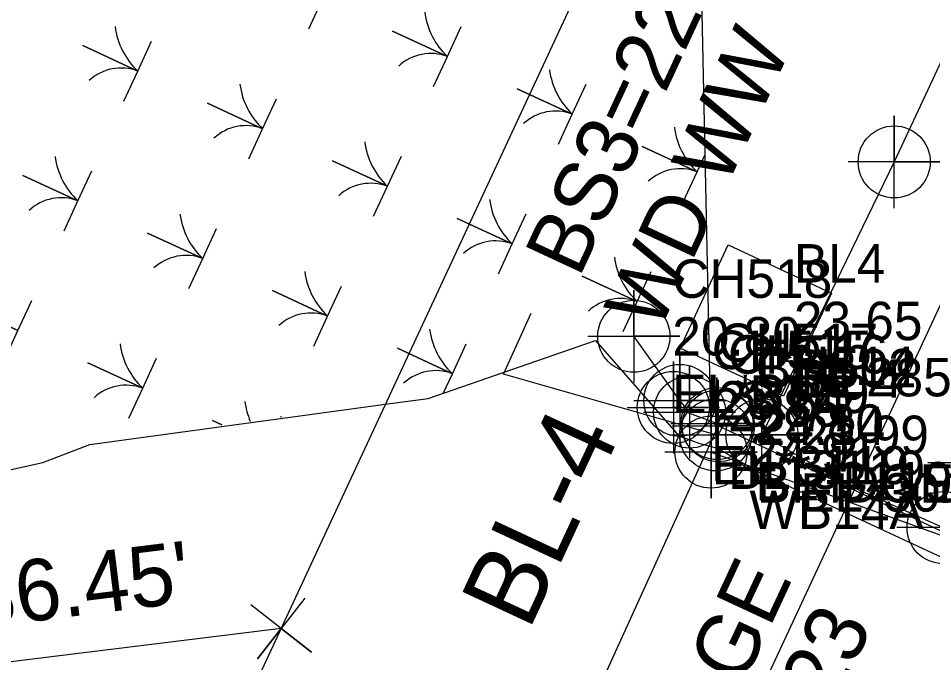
# Model space of a CAD drawing. Extents: x 2532037 to 2533565, y 713396 to 716867.
# Drawn here: x 2532822.3 to 2532881.8, y 715640.6 to 715682.5 of the extents above; entities that cross this region are included whole.
import ezdxf

# ---------------------------------------------------------------- set-up
doc = ezdxf.new("R2010")
doc.units = 0
for name, color, linetype in [('CTL Secondary Horizontal and Vertical CELL', 7, 'Continuous'), ('CTL Secondary Horizontal and Vertical Cogo Comment', 7, 'Continuous'), ('CTL Secondary Horizontal and Vertical Cogo Elevation', 7, 'Continuous'), ('CTL Secondary Horizontal and Vertical Cogo Number', 7, 'Continuous'), ('CTL Secondary Horizontal and Vertical Text', 7, 'Continuous'), ('Exist Environmental Wetland Boundary', 7, 'Continuous'), ('Exist Environmental Wetland Boundary Cogo Comment', 7, 'Continuous'), ('Exist Environmental Wetland Boundary Cogo Elevation', 7, 'Continuous'), ('Exist Environmental Wetland Boundary Cogo Number', 7, 'Continuous'), ('Exist Environmental Wetland Boundary Cogo Point CELL', 7, 'Continuous'), ('Exist Horizontal Alignment', 7, 'Continuous'), ('Exist Hydro Jurisdictional Stream or Body of Water', 7, 'Continuous'), ('Exist Property Corner CELL', 7, 'Continuous'), ('Exist Property Line', 7, 'Continuous'), ('Exist Property Line Text', 7, 'Continuous'), ('Exist Right of Way Line', 7, 'Continuous'), ('Exist Roads Soil', 7, 'Continuous'), ('Exist Roads Soil Cogo Comment', 7, 'Continuous'), ('Exist Roads Soil Cogo Elevation', 7, 'Continuous'), ('Exist Roads Soil Cogo Number', 7, 'Continuous'), ('Exist Roads Soil Cogo Point CELL', 7, 'Continuous'), ('Exist Structure Major Bridge Seat Cogo Point CELL', 7, 'Continuous'), ('Exist Structure Major Bridge Seat Leader', 7, 'Continuous'), ('Exist Structure Major Bridge Seat Top Elevation', 7, 'Continuous'), ('Exist Structure Major Bridge WW', 7, 'Continuous'), ('Exist Structure Major Bridge WW Cogo Comment', 7, 'Continuous'), ('Exist Structure Major Bridge WW Cogo Elevation', 7, 'Continuous'), ('Exist Structure Major Bridge WW Cogo Number', 7, 'Continuous'), ('Exist Structure Major Bridge WW Cogo Point CELL', 7, 'Continuous'), ('Exist Structure Major Bridge WW Text', 7, 'Continuous'), ('Exist Structure Major Deck Tunnel Box Culvert', 7, 'Continuous'), ('Exist Structure Major Deck Tunnel Box Culvert Cogo Comment', 7, 'Continuous'), ('Exist Structure Major Deck Tunnel Box Culvert Cogo Elevation', 7, 'Continuous'), ('Exist Structure Major Deck Tunnel Box Culvert Cogo Number', 7, 'Continuous'), ('Exist Structure Major Deck Tunnel Box Culvert Cogo Point CELL', 7, 'Continuous'), ('Exist Structure Major Deck Tunnel Box Culvert Text', 7, 'Continuous'), ('Scratch_Level_1', 7, 'Continuous')]:
    doc.layers.add(name, color=color, linetype=linetype)

msp = doc.modelspace()

# ---------------------------------------------------------------- linework, layer by layer
at = {"layer": 'CTL Secondary Horizontal and Vertical CELL'}
msp.add_line((2532870.227, 715662.819), (2532870.227, 715662.819), dxfattribs=at)
msp.add_lwpolyline([(2532865.322, 715661.047), (2532868.449, 715667.768), (2532875.181, 715664.636), (2532872.054, 715657.915)], close=True, dxfattribs=at)
at = {"layer": 'Exist Environmental Wetland Boundary'}
for p, q in [((2532866.358, 715700.97), (2532867.338, 715654.282)), ((2532839.356, 715656.559), (2532839.395, 715656.645)), ((2532867.338, 715654.282), (2532887.83, 715646.863))]:
    msp.add_line(p, q, dxfattribs=at)
for points in [[(2532867.177, 715661.939), (2532867.073, 715661.987), (2532867.177, 715661.939)], [(2532835.514, 715656.069), (2532834.912, 715656.346), (2532835.514, 715656.069)]]:
    msp.add_lwpolyline(points, dxfattribs=at)
msp.add_arc((2532841.781, 715658.198), 4.806, 187.34643, 203.20162, dxfattribs=at)
at = {"layer": 'Exist Environmental Wetland Boundary Cogo Point CELL'}
msp.add_lwpolyline([(2532867.338, 715657.282), (2532867.338, 715651.282), (2532867.338, 715654.282), (2532870.338, 715654.282), (2532864.338, 715654.282)], dxfattribs=at)
msp.add_circle((2532867.338, 715654.282), 2.344, dxfattribs=at)
at = {"layer": 'Exist Horizontal Alignment'}
msp.add_line((2532720.816, 715316.862), (2532922.836, 715751.084), dxfattribs=at)
at = {"layer": 'Exist Hydro Jurisdictional Stream or Body of Water'}
msp.add_lwpolyline([(2532806.944, 715649.86), (2532823.862, 715653.608), (2532826.936, 715654.78), (2532846.795, 715657.486), (2532848.935, 715657.763), (2532859.818, 715661.557), (2532865.255, 715655.34), (2532866.545, 715654.873), (2532867.828, 715654.527), (2532870.349, 715653.031), (2532883.272, 715647.025), (2532884.83, 715646.372), (2532885.882, 715645.762), (2532886.539, 715645.426), (2532889.693, 715644.068), (2532889.952, 715644.137), (2532891.522, 715643.982), (2532891.782, 715643.826), (2532896.496, 715640.921), (2532907.078, 715634.646), (2532915.587, 715630.595), (2532919.574, 715628.211), (2532929.47, 715622.835), (2532946.956, 715616.792)], dxfattribs=at)
at = {"layer": 'Exist Property Corner CELL'}
msp.add_line((2532839.376, 715642.813), (2532839.376, 715642.813), dxfattribs=at)
msp.add_lwpolyline([(2532840.913, 715644.784), (2532837.838, 715640.842), (2532839.376, 715642.813), (2532841.347, 715641.275), (2532837.405, 715644.351)], dxfattribs=at)
at = {"layer": 'Exist Property Line'}
msp.add_line((2532839.376, 715642.813), (2532753.576, 715632.211), dxfattribs=at)
at = {"layer": 'Exist Right of Way Line'}
msp.add_line((2532693.616, 715329.517), (2532895.636, 715763.738), dxfattribs=at)
at = {"layer": 'Exist Roads Soil'}
msp.add_lwpolyline([(2533033.002, 715963.552), (2533014.441, 715935.484), (2532992.666, 715901.095), (2532976.471, 715871.314), (2532962.05, 715845.129), (2532943.271, 715807.995), (2532921.982, 715764.363), (2532902.685, 715724.284), (2532889.068, 715694.204), (2532879.255, 715673.169), (2532870.648, 715655.411), (2532876.571, 715652.013), (2532882.435, 715649.375)], dxfattribs=at)
at = {"layer": 'Exist Roads Soil Cogo Point CELL'}
for points in [[(2532879.255, 715670.169), (2532879.255, 715676.169), (2532879.255, 715673.169), (2532882.255, 715673.169), (2532876.255, 715673.169)], [(2532870.648, 715652.411), (2532870.648, 715658.411), (2532870.648, 715655.411), (2532873.648, 715655.411), (2532867.648, 715655.411)], [(2532884.446, 715650.582), (2532884.446, 715656.582), (2532884.446, 715653.582), (2532887.446, 715653.582), (2532881.446, 715653.582)], [(2532882.435, 715646.375), (2532882.435, 715652.375), (2532882.435, 715649.375), (2532885.435, 715649.375), (2532879.435, 715649.375)]]:
    msp.add_lwpolyline(points, dxfattribs=at)
for centre in [(2532879.255, 715673.169), (2532870.648, 715655.411), (2532882.435, 715649.375)]:
    msp.add_circle(centre, 2.344, dxfattribs=at)
at = {"layer": 'Exist Structure Major Bridge Seat Cogo Point CELL'}
msp.add_lwpolyline([(2532864.642, 715655.407), (2532870.642, 715655.407), (2532867.642, 715655.407), (2532867.642, 715658.407), (2532867.642, 715652.407)], dxfattribs=at)
msp.add_lwpolyline([(2532864.642, 715655.407), (2532870.642, 715655.407), (2532867.642, 715655.407), (2532867.642, 715658.407), (2532867.642, 715652.407)], dxfattribs=at)
msp.add_circle((2532867.642, 715655.407), 2.344, dxfattribs=at)
msp.add_circle((2532867.642, 715655.407), 2.344, dxfattribs=at)
at = {"layer": 'Exist Structure Major Bridge Seat Leader'}
msp.add_lwpolyline([(2532867.642, 715655.407), (2532853.84, 715659.353), (2532855.64, 715663.323)], dxfattribs=at)
at = {"layer": 'Exist Structure Major Bridge WW'}
msp.add_line((2532867.727, 715656.142), (2532864.888, 715657.19), dxfattribs=at)
msp.add_lwpolyline([(2532865.941, 715656.888), (2532865.312, 715657.652), (2532862.318, 715661.821)], dxfattribs=at)
at = {"layer": 'Exist Structure Major Bridge WW Cogo Point CELL'}
for points in [[(2532859.318, 715661.821), (2532865.318, 715661.821), (2532862.318, 715661.821), (2532862.318, 715664.821), (2532862.318, 715658.821)], [(2532862.312, 715657.652), (2532868.312, 715657.652), (2532865.312, 715657.652), (2532865.312, 715660.652), (2532865.312, 715654.652)], [(2532861.888, 715657.19), (2532867.888, 715657.19), (2532864.888, 715657.19), (2532864.888, 715660.19), (2532864.888, 715654.19)], [(2532862.941, 715656.888), (2532868.941, 715656.888), (2532865.941, 715656.888), (2532865.941, 715659.888), (2532865.941, 715653.888)], [(2532864.727, 715656.142), (2532870.727, 715656.142), (2532867.727, 715656.142), (2532867.727, 715659.142), (2532867.727, 715653.142)]]:
    msp.add_lwpolyline(points, dxfattribs=at)
for centre in [(2532862.318, 715661.821), (2532865.312, 715657.652), (2532864.888, 715657.19), (2532865.941, 715656.888), (2532867.727, 715656.142)]:
    msp.add_circle(centre, 2.344, dxfattribs=at)
at = {"layer": 'Exist Structure Major Deck Tunnel Box Culvert'}
msp.add_lwpolyline([(2532885.805, 715647.494), (2532867.812, 715655.999), (2532853.101, 715623.682), (2532870.979, 715615.38), (2532885.805, 715647.494)], dxfattribs=at)
at = {"layer": 'Exist Structure Major Deck Tunnel Box Culvert Cogo Point CELL'}
msp.add_lwpolyline([(2532864.812, 715655.999), (2532870.812, 715655.999), (2532867.812, 715655.999), (2532867.812, 715658.999), (2532867.812, 715652.999)], dxfattribs=at)
msp.add_lwpolyline([(2532864.812, 715655.999), (2532870.812, 715655.999), (2532867.812, 715655.999), (2532867.812, 715658.999), (2532867.812, 715652.999)], dxfattribs=at)
msp.add_circle((2532867.812, 715655.999), 2.344, dxfattribs=at)
msp.add_circle((2532867.812, 715655.999), 2.344, dxfattribs=at)
at = {"layer": 'Scratch_Level_1'}
for points in [[(2532841.167, 715681.823), (2532842.068, 715683.775), (2532838.486, 715685.429), (2532842.068, 715683.775), (2532842.969, 715685.728)], [(2532849.288, 715678.073), (2532850.189, 715680.026), (2532846.608, 715681.679), (2532850.189, 715680.026), (2532851.091, 715681.978)], [(2532829.147, 715677.128), (2532830.048, 715679.08), (2532826.466, 715680.734), (2532830.048, 715679.08), (2532830.949, 715681.033)], [(2532857.409, 715674.324), (2532858.311, 715676.276), (2532854.729, 715677.93), (2532858.311, 715676.276), (2532859.212, 715678.229)], [(2532837.268, 715673.378), (2532838.17, 715675.331), (2532834.588, 715676.984), (2532838.17, 715675.331), (2532839.071, 715677.283)], [(2532865.531, 715670.575), (2532866.432, 715672.527), (2532862.85, 715674.181), (2532866.432, 715672.527), (2532866.932, 715673.61)], [(2532845.39, 715669.629), (2532846.291, 715671.581), (2532842.709, 715673.235), (2532846.291, 715671.581), (2532847.192, 715673.534)], [(2532825.248, 715668.683), (2532826.15, 715670.636), (2532822.568, 715672.289), (2532826.15, 715670.636), (2532827.051, 715672.588)], [(2532853.511, 715665.88), (2532854.412, 715667.832), (2532850.831, 715669.486), (2532854.412, 715667.832), (2532855.314, 715669.785)], [(2532833.37, 715664.934), (2532834.271, 715666.886), (2532830.689, 715668.54), (2532834.271, 715666.886), (2532835.172, 715668.839)], [(2532861.632, 715662.13), (2532862.534, 715664.083), (2532858.952, 715665.736), (2532862.534, 715664.083), (2532863.435, 715666.035)], [(2532841.491, 715661.185), (2532842.393, 715663.137), (2532838.811, 715664.791), (2532842.393, 715663.137), (2532843.294, 715665.09)], [(2532821.35, 715660.239), (2532822.251, 715662.192), (2532818.669, 715663.845), (2532822.251, 715662.192), (2532823.153, 715664.144)], [(2532849.937, 715658.138), (2532850.514, 715659.388), (2532846.932, 715661.041), (2532850.514, 715659.388), (2532851.415, 715661.34)], [(2532829.471, 715656.49), (2532830.373, 715658.442), (2532826.791, 715660.096), (2532830.373, 715658.442), (2532831.274, 715660.395)]]:
    msp.add_lwpolyline(points, dxfattribs=at)
for centre, radius, start, end in [((2532853.477, 715683.531), 4.806, 187.34643, 226.84116), ((2532833.335, 715682.586), 4.806, 187.34643, 226.84116), ((2532849.106, 715677.149), 3.075, 69.35932, 132.75394), ((2532828.964, 715676.203), 3.075, 69.35932, 132.75394), ((2532861.598, 715679.782), 4.806, 187.34643, 226.84116), ((2532841.457, 715678.836), 4.806, 187.34643, 226.84116), ((2532857.227, 715673.399), 3.075, 69.35932, 132.75394), ((2532837.086, 715672.454), 3.075, 69.35932, 132.75394), ((2532869.719, 715676.033), 4.806, 187.34643, 226.84116), ((2532849.578, 715675.087), 4.806, 187.34643, 226.84116), ((2532829.437, 715674.141), 4.806, 187.34643, 226.84116), ((2532865.348, 715669.65), 3.075, 69.35932, 132.75394), ((2532845.207, 715668.704), 3.075, 69.35932, 132.75394), ((2532825.066, 715667.759), 3.075, 69.35932, 132.75394), ((2532857.7, 715671.338), 4.806, 187.34643, 226.84116), ((2532837.558, 715670.392), 4.806, 187.34643, 226.84116), ((2532853.329, 715664.955), 3.075, 69.35932, 132.75394), ((2532833.187, 715664.009), 3.075, 69.35932, 132.75394), ((2532865.821, 715667.588), 4.806, 187.34643, 226.84116), ((2532845.68, 715666.643), 4.806, 187.34643, 226.84116), ((2532861.45, 715661.206), 3.075, 69.35932, 132.75394), ((2532841.309, 715660.26), 3.075, 69.35932, 132.75394), ((2532853.801, 715662.893), 4.806, 187.34643, 226.84116), ((2532833.66, 715661.948), 4.806, 187.34643, 226.84116), ((2532849.43, 715656.511), 3.075, 69.35932, 132.75394), ((2532829.289, 715655.565), 3.075, 69.35932, 132.75394)]:
    msp.add_arc(centre, radius, start, end, dxfattribs=at)

# ---------------------------------------------------------------- texts
at = {"layer": 'CTL Secondary Horizontal and Vertical Cogo Comment'}
msp.add_text('BL-4', height=2.5, dxfattribs=at).set_placement((2532872.727, 715657.819))
msp.add_text('BL-4', height=2.5, dxfattribs=at).set_placement((2532872.727, 715657.819))
at = {"layer": 'CTL Secondary Horizontal and Vertical Cogo Elevation'}
msp.add_text('23.65', height=2.5, dxfattribs=at).set_placement((2532872.727, 715661.569))
msp.add_text('23.65', height=2.5, dxfattribs=at).set_placement((2532872.727, 715661.569))
at = {"layer": 'CTL Secondary Horizontal and Vertical Cogo Number'}
msp.add_text('BL4', height=2.5, dxfattribs=at).set_placement((2532872.727, 715665.319))
msp.add_text('BL4', height=2.5, dxfattribs=at).set_placement((2532872.727, 715665.319))
at = {"layer": 'CTL Secondary Horizontal and Vertical Text'}
msp.add_text('BL-4', height=5, rotation=65.05, dxfattribs=at).set_placement((2532855.476, 715642.587))
at = {"layer": 'Exist Environmental Wetland Boundary Cogo Comment'}
msp.add_text('WB14A', height=2.5, dxfattribs=at).set_placement((2532869.838, 715649.282))
at = {"layer": 'Exist Environmental Wetland Boundary Cogo Elevation'}
msp.add_text('24.91', height=2.5, dxfattribs=at).set_placement((2532869.838, 715653.032))
at = {"layer": 'Exist Environmental Wetland Boundary Cogo Number'}
msp.add_text('RR5', height=2.5, dxfattribs=at).set_placement((2532869.838, 715656.782))
at = {"layer": 'Exist Property Line Text'}
msp.add_text("86.45'", height=4, rotation=7.04441, dxfattribs=at).set_placement((2532819.355, 715642.794))
at = {"layer": 'Exist Roads Soil Cogo Comment'}
msp.add_text('EL*3005', height=2.5, dxfattribs=at).set_placement((2532873.148, 715650.411))
at = {"layer": 'Exist Roads Soil Cogo Elevation'}
msp.add_text('23.99', height=2.5, dxfattribs=at).set_placement((2532873.148, 715654.161))
at = {"layer": 'Exist Roads Soil Cogo Number'}
msp.add_text('HL285', height=2.5, dxfattribs=at).set_placement((2532873.148, 715657.911))
at = {"layer": 'Exist Structure Major Bridge Seat Top Elevation'}
msp.add_text("BS3=22.07'", height=4, rotation=65.05, dxfattribs=at).set_placement((2532858.753, 715665.558))
at = {"layer": 'Exist Structure Major Bridge WW Cogo Comment'}
for s, p in [('EL*3119', (2532864.818, 715656.821)), ('EL*3119', (2532867.388, 715652.19)), ('BL*3119', (2532868.441, 715651.888)), ('BL*3119', (2532870.227, 715651.142))]:
    msp.add_text(s, height=2.5, dxfattribs=at).set_placement(p)
at = {"layer": 'Exist Structure Major Bridge WW Cogo Elevation'}
for s, p in [('20.80', (2532864.818, 715660.571)), ('23.84', (2532867.812, 715656.402)), ('23.86', (2532867.388, 715655.94)), ('23.77', (2532868.441, 715655.638)), ('23.80', (2532870.227, 715654.892))]:
    msp.add_text(s, height=2.5, dxfattribs=at).set_placement(p)
at = {"layer": 'Exist Structure Major Bridge WW Cogo Number'}
for s, p in [('CH518', (2532864.818, 715664.321)), ('CH515', (2532867.388, 715659.69)), ('CH517', (2532867.812, 715660.152)), ('CH516', (2532868.441, 715659.388)), ('CH514', (2532870.227, 715658.642))]:
    msp.add_text(s, height=2.5, dxfattribs=at).set_placement(p)
at = {"layer": 'Exist Structure Major Bridge WW Text'}
msp.add_text('WD WW', height=4, rotation=65.05, dxfattribs=at).set_placement((2532863.931, 715662.007))
at = {"layer": 'Exist Structure Major Deck Tunnel Box Culvert Cogo Comment'}
msp.add_text('BRIDGE DECK 3', height=2.5, dxfattribs=at).set_placement((2532870.312, 715650.999))
at = {"layer": 'Exist Structure Major Deck Tunnel Box Culvert Cogo Elevation'}
msp.add_text('24.14', height=2.5, dxfattribs=at).set_placement((2532870.312, 715654.749))
msp.add_text('24.14', height=2.5, dxfattribs=at).set_placement((2532870.312, 715654.749))
at = {"layer": 'Exist Structure Major Deck Tunnel Box Culvert Cogo Number'}
for s in ['CH502', 'BD3']:
    msp.add_text(s, height=2.5, dxfattribs=at).set_placement((2532870.312, 715658.499))
at = {"layer": 'Exist Structure Major Deck Tunnel Box Culvert Text'}
for s, p in [('BRIDGE', (2532864, 715627.432)), ('NO. 123', (2532869.46, 715624.944))]:
    msp.add_text(s, height=4, rotation=65.05, dxfattribs=at).set_placement(p)

doc.saveas('drawing.dxf')
